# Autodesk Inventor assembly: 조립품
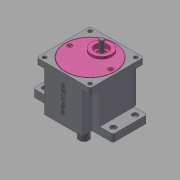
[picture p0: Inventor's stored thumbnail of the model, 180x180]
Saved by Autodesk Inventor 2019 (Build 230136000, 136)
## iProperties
Created: 2020-01
Part Number: 조립품
Material: 일반
Document SubType Name: Assembly
Designer: 323-17
Author: 323-17
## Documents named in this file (9)
- C:\Users\323-17\Desktop\700119V1005\조립품.iam
- C:\Users\323-17\Desktop\700119V1005\본체.ipt
- C:\Users\323-17\Desktop\700119V1005\서브 축.ipt
- C:\Users\323-17\Desktop\700119V1005\베어링 6003.ipt
- C:\Users\323-17\Desktop\700119V1005\베어링 608.ipt
- C:\Users\323-17\Desktop\700119V1005\메인 축.ipt
- C:\Users\323-17\Desktop\700119V1005\오일 실 17 32 8.ipt
- C:\Users\323-17\Desktop\700119V1005\커버.ipt
- C:\Users\323-17\Desktop\700119V1005\볼트 M4.ipt
